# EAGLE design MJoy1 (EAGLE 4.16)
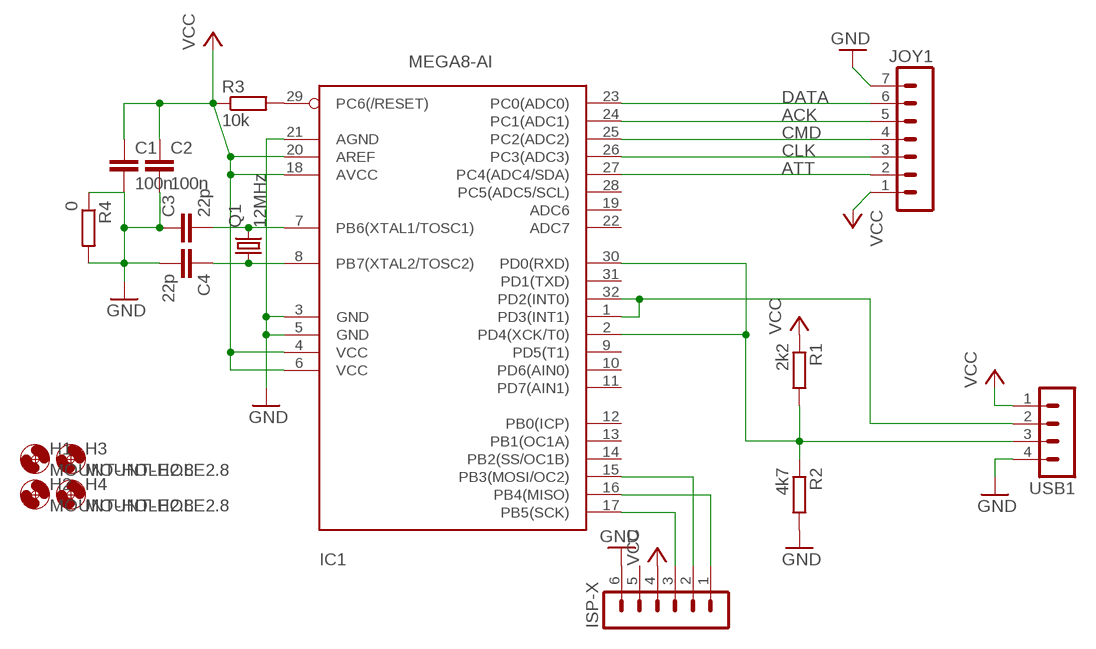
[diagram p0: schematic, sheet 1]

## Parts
C1  100n  C-EUC1206  [C1206]
C2  100n  C-EUC1206  [C1206]
C3  22p  C-EUC1206  [C1206]
C4  22p  C-EUC1206  [C1206]
H1  MOUNT-HOLE2.8  [2,8]
H2  MOUNT-HOLE2.8  [2,8]
H3  MOUNT-HOLE2.8  [2,8]
H4  MOUNT-HOLE2.8  [2,8]
IC1  MEGA8-AI  [TQFP32-08]
ISP-X  MA06-1  [MA06-1]
JOY1  MA07-1  [MA07-1]
Q1  12MHz  CRYTALHC49U-V  [HC49U-V]
R1  2k2  R-EU_M1206  [M1206]
R2  4k7  R-EU_M1206  [M1206]
R3  10k  R-EU_M1206  [M1206]
R4  0  R-EU_M1206  [M1206]
USB1  MA04-1  [MA04-1]

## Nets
ACK: IC1.24(PC1(ADC1)) JOY1.5
ATT: IC1.27(PC4(ADC4/SDA)) JOY1.2
CLK: IC1.26(PC3(ADC3)) JOY1.3
CMD: IC1.25(PC2(ADC2)) JOY1.4
DATA: IC1.23(PC0(ADC0)) JOY1.6
GND: C1.2 C2.2 C3.1 C4.2 IC1.3(GND) IC1.5(GND) IC1.21(AGND) ISP-X.6 JOY1.7 R2.2 R4.1 R4.2 USB1.4
MISO: IC1.16(PB4(MISO)) ISP-X.1
MOSI: IC1.15(PB3(MOSI/OC2)) ISP-X.2
N$1: C3.2 IC1.7(PB6(XTAL1/TOSC1)) Q1.2
N$2: C4.1 IC1.8(PB7(XTAL2/TOSC2)) Q1.1
N$6: IC1.2(PD4(XCK/T0)) IC1.30(PD0(RXD)) R1.2 R2.1 USB1.3
N$7: IC1.1(PD3(INT1)) IC1.32(PD2(INT0)) USB1.2
RESET: IC1.29(PC6(/RESET)) R3.2
SCK: IC1.17(PB5(SCK)) ISP-X.3
VCC: C1.1 C2.1 IC1.4(VCC) IC1.6(VCC) IC1.18(AVCC) IC1.20(AREF) ISP-X.4 JOY1.1 R1.1 R3.1 USB1.1
Unconnected: IC1.9(PD5(T1)) IC1.10(PD6(AIN0)) IC1.11(PD7(AIN1)) IC1.12(PB0(ICP)) IC1.13(PB1(OC1A)) IC1.14(PB2(SS/OC1B)) IC1.19(ADC6) IC1.22(ADC7) IC1.28(PC5(ADC5/SCL)) IC1.31(PD1(TXD)) ISP-X.5

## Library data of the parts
C1-C4 = rcl:C-EU: CAPACITOR, European symbol
H1-H4 = holes:MOUNT-HOLE: MOUNTING HOLE with drill center marker
IC1 = atmel:MEGA8: MICROCONTROLLER 8 Kbytes FLASH 1 kbytes SRAM 512 bytes EEPROM USART 6-channel 10 bit ADC 2-channel 8 bit ADC Source: avr.lbr
ISP-X = con-lstb:MA06-1: PIN HEADER
JOY1 = con-lstb:MA07-1: PIN HEADER
Q1 = crystal:CRYTAL: CRYSTAL
R1-R4 = rcl:R-EU_: RESISTOR, European symbol
USB1 = con-lstb:MA04-1: PIN HEADER

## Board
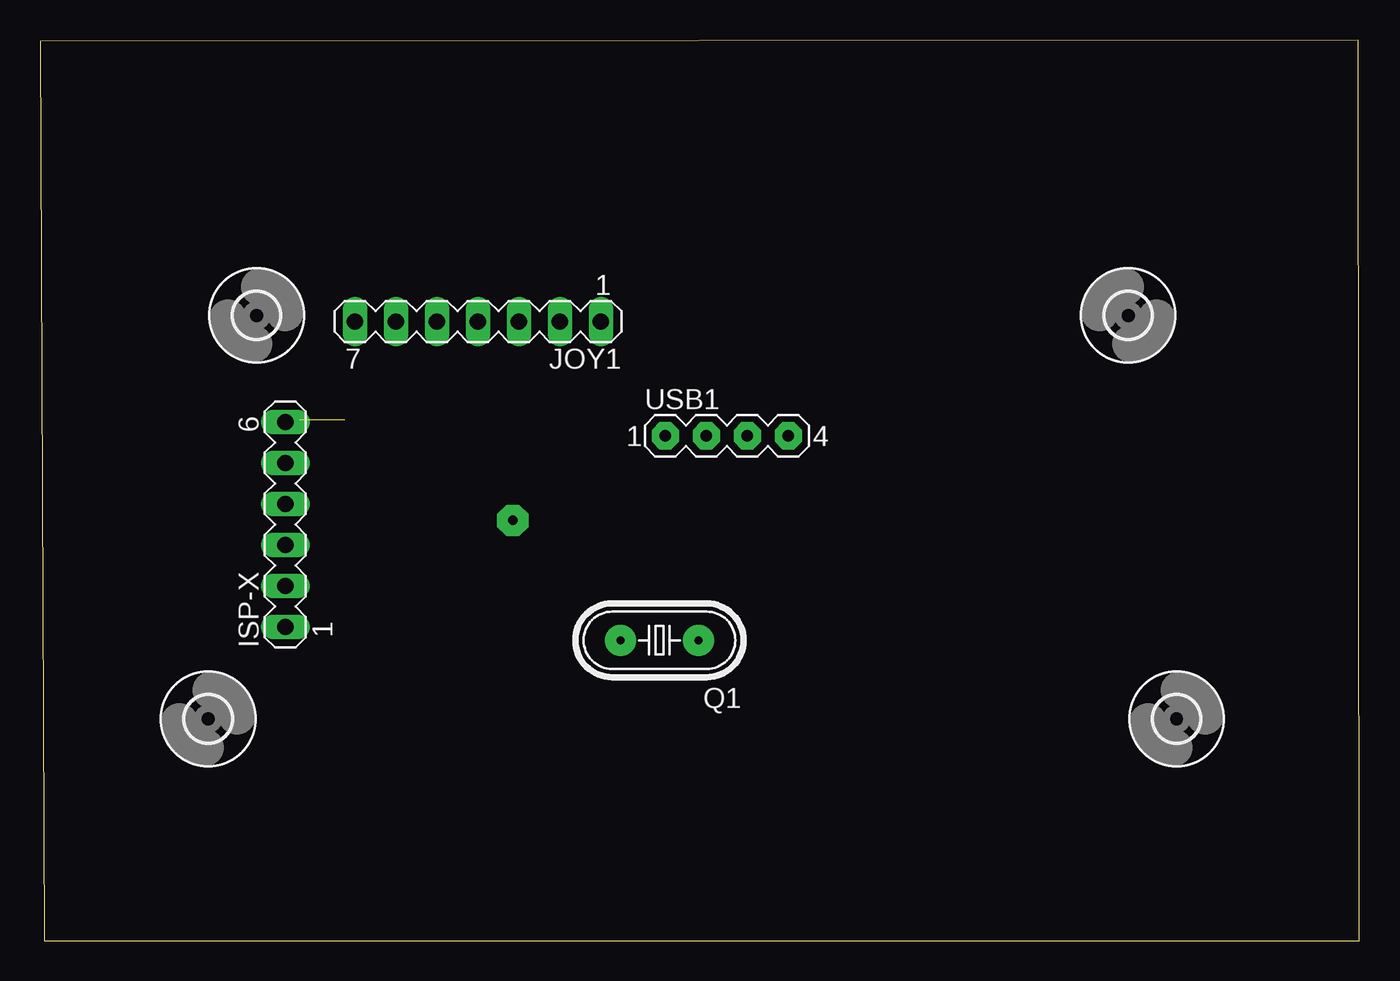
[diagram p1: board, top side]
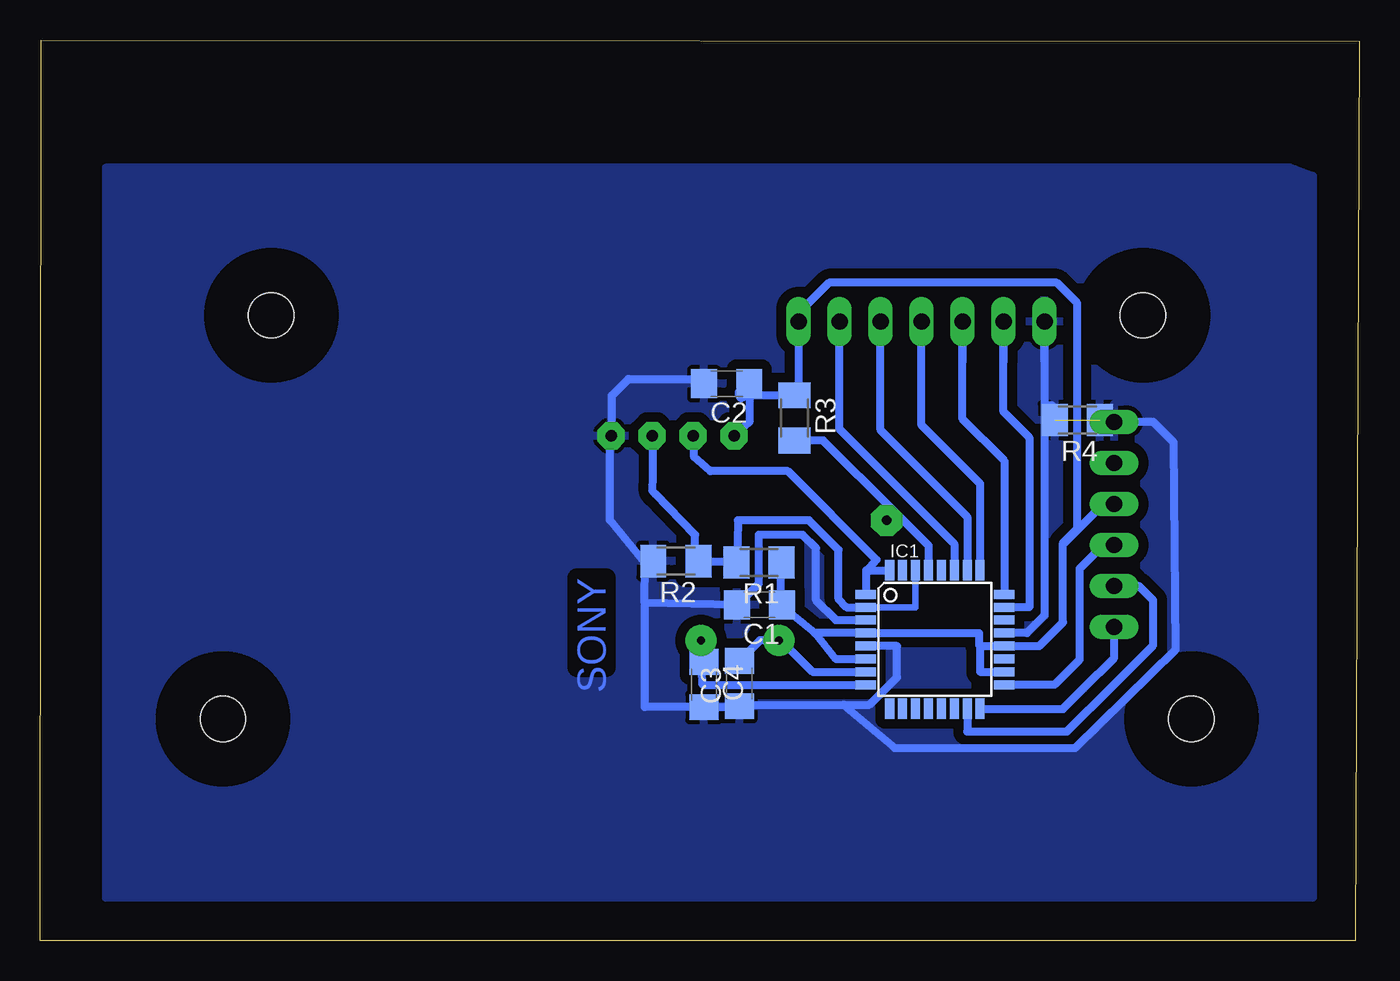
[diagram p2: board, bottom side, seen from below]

Size 81.7 x 55.78 mm. Coordinates in mm from the lower left corner, seen from the top.
Outline: 0.25,0 81.7,0 81.64,55.78 0,55.71 0.25,0
Copper layers (1*16): Top 0.035mm / dielectric 1.5mm / Bottom 0.035mm
Design rules "default": minimum track width 10mil, minimum drill 24mil, track to track 8mil, track to pad 8mil, pad to pad 8mil, via to via 8mil, smd to smd 8mil, copper to edge 40mil, drill to drill 8mil, minimum pad ring 10mil, minimum via ring 8mil, stop-mask expansion 4mil, vias tented up to drill 0mil, thermal gap 10mil

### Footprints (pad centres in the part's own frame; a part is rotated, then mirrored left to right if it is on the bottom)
C1206 = smd 1.6 x 1.8: 1 -1.4,0; 2 1.4,0
2,8 = hole 2.8: 0,0
TQFP32-08 = smd 1.27 x 0.559: 1 -4.293,2.8; 2 -4.293,2; 3 -4.293,1.2; 4 -4.293,0.4; 5 -4.293,-0.4; 6 -4.293,-1.2; 7 -4.293,-2; 8 -4.293,-2.8; 17 4.293,-2.8; 18 4.293,-2; 19 4.293,-1.2; 20 4.293,-0.4; 21 4.293,0.4; 22 4.293,1.2; 23 4.293,2; 24 4.293,2.8 | smd 0.559 x 1.27: 9 -2.8,-4.293; 10 -2,-4.293; 11 -1.2,-4.293; 12 -0.4,-4.293; 13 0.4,-4.293; 14 1.2,-4.293; 15 2,-4.293; 16 2.8,-4.293; 25 2.8,4.293; 26 2,4.293; 27 1.2,4.293; 28 0.4,4.293; 29 -0.4,4.293; 30 -1.2,4.293; 31 -2,4.293; 32 -2.8,4.293
MA06-1 = drill 1.016 long: 1 -6.35,0; 2 -3.81,0; 3 -1.27,0; 4 1.27,0; 5 3.81,0; 6 6.35,0
MA07-1 = drill 1.016 long: 1 -7.62,0; 2 -5.08,0; 3 -2.54,0; 4 0,0; 5 2.54,0; 6 5.08,0; 7 7.62,0
HC49U-V = drill 0.5 pad 1.93 round: 1 -2.413,0; 2 2.413,0
M1206 = smd 1.6 x 2: 1 -1.4,0; 2 1.4,0
MA04-1 = drill 0.7 pad 1.676 octagon: 1 -3.81,0; 2 -1.27,0; 3 1.27,0; 4 3.81,0

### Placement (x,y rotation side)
C1  37.15,20.8 180 bottom
C2  39.18,34.51 180 bottom
C3  38.4,15.92 90 bottom
C4  40.59,15.86 270 bottom
H1  13.39,38.73 0 top
H2  67.39,38.73 90 top
H3  10.39,13.73 0 top
H4  70.39,13.73 0 top
IC1  26.28,18.65 0 bottom
ISP-X  15.17,25.78 90 top
JOY1  27.11,38.35 180 top
Q1  38.35,18.6 180 top
R1  37.18,23.43 180 bottom
R2  42.33,23.51 180 bottom
R3  34.98,32.38 270 bottom
R4  17.46,32.26 180 bottom
USB1  42.53,31.28 0 top

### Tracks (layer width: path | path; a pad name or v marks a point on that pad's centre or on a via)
ACK
  Bottom 0.508: IC1.24 21.99,29.74 24.57,32.32 JOY1.5 24.57,35.88
ATT
  Bottom 0.508: JOY1.2 32.19,31.69 25.08,24.57 25.08,22.8 IC1.27
CLK
  Bottom 0.508: IC1.26 24.28,26.26 29.65,31.62 JOY1.3
CMD
  Bottom 0.508: IC1.25 23.48,28.31 27.11,31.94 JOY1.4
DATA
  Bottom 0.508: IC1.23 20.44,20.65 20.44,31.18 22.03,32.76 JOY1.6 22.03,35.88
GND  (1 unrouted)
  Bottom 0.508: IC1.5 28.63,18.25 28.63,16.32 30.35,14.6 31.94,14.6 | C4.2 38.41,14.46 38.41,14.52 C3.1 38.46,14.52 38.54,14.6 31.94,14.6 | R2.2 43.75,23.45 44.25,23.39 | 44.25,23.39 44.27,20.92 C1.2 38.48,20.8 38.48,20.83 37.21,22.1 37.21,25.14 34.48,25.14 33.65,24.32 33.65,21.08 32.42,19.85 IC1.3 | 19.49,35.88 JOY1.7 19.49,20.14 20.58,19.05 IC1.21 | 46.41,30.26 46.29,31.62 | 46.41,30.26 USB1.4 46.29,31.58 46.29,33.78 45.27,34.8 40.34,34.8 C2.2 | 44.25,23.39 46.41,26.06 46.41,30.26 | 44.25,20.95 44.25,14.48 40.7,14.48 | 40.06,34.8 40.83,34.54 | 31.94,14.6 28.76,11.94 17.58,11.94 11.36,18.03 11.49,30.86 12.76,32.13 15.04,32.13 15.04,32.38 15.93,32.38 15.93,32.26 R4.1 15.17,32.26 ISP-X.6 15.17,32 | R4.2 18.98,32.26 18.98,33.15 19.24,33.15
  pour Bottom (isolate 0.61): 4.25,47.88 77.66,47.88 77.66,2.67 2.85,2.67 2.85,47.37
MISO
  Bottom 0.508: ISP-X.1 15.17,17.52 17.08,15.62 18.35,14.35 23.48,14.35 IC1.16
MOSI
  Bottom 0.508: IC1.15 24.28,12.95 18.09,12.95 15.3,15.75 12.76,18.29 12.76,21.08 13.65,21.97 ISP-X.2
N$1
  Bottom 0.508: IC1.7 33.86,16.65 35.81,18.6 Q1.2 37.13,18.6 38.41,17.32 | 38.41,17.32 38.41,17.27 | 38.41,17.32 C3.2
N$2
  Bottom 0.508: IC1.8 40.68,15.85 40.77,18.48 Q1.1 40.7,18.6 40.7,17.26 C4.1
N$6
  Bottom 0.406: IC1.30 27.49,22.99 | IC1.30 | IC1.2 27.49,20.65 IC1.30
  Bottom 0.508: 41.14,23.49 R2.1 39.19,23.45 41.14,23.49 | 41.14,23.49 R1.2 38.54,23.49 38.48,22.96 38.5,24.68 38.49,26.03 34.07,26.03 32.25,24.21 32.25,21.15 31.76,20.65 IC1.2 | 41.14,23.49 41.14,25.14 43.6,27.67 43.76,27.83 43.75,28.83 43.75,30.46 USB1.3 | 41.14,23.49 39.11,23.49
N$7
  Bottom 0.508: 30.54,22.86 29.9,23.6 35.39,29.08 40.21,29.08 41.21,29.95 41.21,31.2 USB1.2 | IC1.1 30.54,21.45 30.54,22.86 | IC1.32 30.54,22.95 30.54,22.86
RESET  (via drill 0.6 pad 1.93)
  Bottom 0.508: IC1.29 26.68,24.46 28.76,26.54 | 28.76,26.54 33.21,30.99 34.6,30.99 34.73,30.86 34.85,30.98 R3.2 | 28.76,26.54 28.89,26.54 28.89,26.16 v29.27,26.03
SCK
  Bottom 0.508: IC1.17 18.87,15.85 17.33,17.4 17.33,23.03 15.85,24.51 ISP-X.3
VCC
  Bottom 0.508: IC1.6 32.44,17.45 33.71,19.05 | 30.54,19.05 33.71,19.05 | IC1.4 30.54,19.05 | 23.43,18.28 23.41,18.25 IC1.20 19.81,18.25 18.35,19.72 18.35,24.54 | 23.43,18.28 23.47,18.31 23.49,18.31 23.49,16.65 IC1.18 | R1.1 35.81,23.43 35.81,20.76 | 33.71,19.05 35.81,20.76 | 30.54,19.05 28.66,19.05 28.52,19.05 23.55,19.05 23.55,18.29 23.43,18.29 23.43,18.28 | USB1.1 37.78,32.11 37.78,33.8 38.33,33.72 38.29,33.59 38.41,33.78 | 38.41,33.78 38.16,33.66 C2.1 38.42,34.04 38.41,33.78 | 38.41,33.78 35.23,33.78 R3.1 34.73,34.04 34.73,37.59 | 34.73,37.59 JOY1.1 | ISP-X.4 15.84,27.05 18.35,24.54 | 34.73,37.59 34.73,38.88 32.84,40.77 18.73,40.77 17.46,39.5 17.46,25.53 18.35,24.64 18.35,24.54 | 36,20.76 36,20.8 C1.1 | 35.81,20.76 36,20.76 | 36,20.76 36,20.7

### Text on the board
Bottom: SONY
